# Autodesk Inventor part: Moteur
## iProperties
Author: Philippe
Created: 2002-01
Part Number: Moteur
Material: Par défaut
Document SubType Name: Modélisation
Designer: Philippe
Control State: 0
Master: False
Checked Out: False
PropertySet Name: Design Tracking Control
Shininess: 20.0
Angle Display Precision: 2
Document Length Units: 11269
Document Angle Units: 11283
Document Time Units: 11279
Document Mass Units: 11290
Document Length Units Precision: 3
Document Angle Units Precision: 2
Compacted: False
PropertySet Name: _Private Model Information
Density: 0.0
Volumn: 0.0
Area: 0.0
PropertySet Name: Model Information
